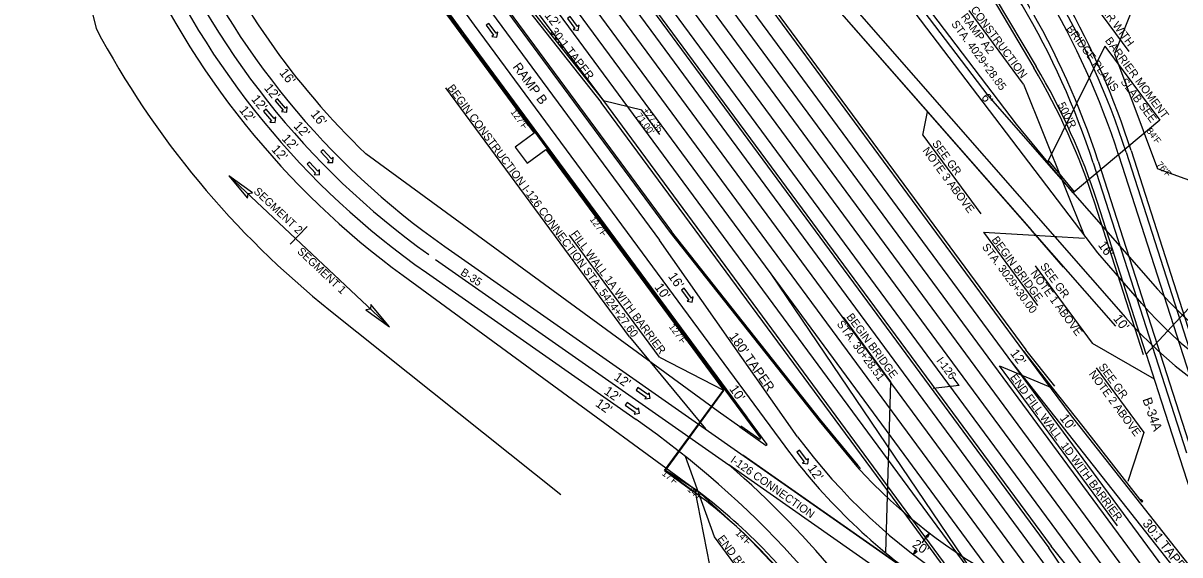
# Model space of a CAD drawing. Extents: x 1966090 to 1975830, y 788086 to 801233.
# Drawn here: x 1970278 to 1971145, y 796167 to 796566 of the extents above; entities that cross this region are included whole.
import ezdxf

# ---------------------------------------------------------------- set-up
doc = ezdxf.new("R2010")
doc.units = 0
for name, color, linetype in [('BR_PRESTRESSED BEAM', 7, 'Continuous'), ('BR_PROPOSED_DRAINAGE', 7, 'Continuous'), ('BR_REBAR', 7, 'Continuous'), ('RD_EX_Driveway_txCode', 7, 'Continuous'), ('RD_EX_RW_TX', 7, 'Continuous'), ('RD_EX_SU_Gas', 7, 'Continuous'), ('RD_EX_SU_H2O', 7, 'Continuous'), ('RD_EX_TX_Dam_ELEV', 7, 'Continuous'), ('RD_PD_PaveShd', 7, 'Continuous'), ('RD_PD_RW_TX', 7, 'Continuous'), ('RD_Sketch6', 7, 'Continuous'), ('RD_Sketch8', 7, 'Continuous'), ('RD_Sketch9', 7, 'Continuous')]:
    doc.layers.add(name, color=color, linetype=linetype)

msp = doc.modelspace()

# ---------------------------------------------------------------- linework, layer by layer
at = {"layer": 'BR_PRESTRESSED BEAM'}
for p, q in [((1970787.81, 796798.98), (1971022.06, 796490.5)), ((1970738.79, 796747.3), (1971033.24, 796411.1)), ((1971022.06, 796490.5), (1971045.64, 796461.99)), ((1971108.26, 796470.58), (1971155.03, 796325.07)), ((1971057.61, 796383.26), (1971033.24, 796411.1)), ((1971119.45, 796318.1), (1971130.78, 796282.88)), ((1971049.03, 796292.83), (1971071.97, 796263.8)), ((1971130.78, 796282.88), (1971152.81, 796214.33)), ((1971071.97, 796263.8), (1971116.28, 796207.05)), ((1971115.64, 796209.09), (1971115.05, 796208.63)), ((1971115.05, 796208.63), (1971116.28, 796207.05)), ((1971117.07, 796207.67), (1971115.64, 796209.09)), ((1971116.28, 796207.05), (1971117.07, 796207.67))]:
    msp.add_line(p, q, dxfattribs=at)
msp.add_arc((1970527.52, 796283.91), 610, 17.81866, 41.03874, dxfattribs=at)
at = {"layer": 'BR_PROPOSED_DRAINAGE'}
for p, q in [((1970591.97, 796577.07), (1970651.22, 796496.51)), ((1970651.22, 796496.51), (1970660.72, 796483.61)), ((1970660.72, 796483.61), (1970646.71, 796473.28)), ((1970646.71, 796473.28), (1970655.61, 796461.21)), ((1970655.61, 796461.21), (1970669.62, 796471.54)), ((1970669.62, 796471.54), (1970710.56, 796416.02)), ((1970710.56, 796416.02), (1970769.89, 796335.53)), ((1970769.89, 796335.53), (1970802.67, 796291.06)), ((1970802.67, 796291.06), (1970758.92, 796231.3)), ((1970758.92, 796231.3), (1970782.69, 796216.13)), ((1970782.69, 796216.13), (1970818.81, 796183)), ((1970818.81, 796183), (1970852.53, 796147.43))]:
    msp.add_line(p, q, dxfattribs=at)
for points in [[(1971119.79, 796603.55), (1971095.61, 796543.15), (1971127.85, 796457)], [(1971246.98, 796386.46), (1971192.99, 796433.53), (1971127.85, 796457)]]:
    msp.add_lwpolyline(points, dxfattribs=at)
at = {"layer": 'BR_REBAR'}
for p, q in [((1970693.11, 796777.07), (1971029.24, 796321.12)), ((1970691.5, 796775.88), (1971027.63, 796319.93)), ((1970540.77, 796722.24), (1970711.09, 796506.63)), ((1971003.51, 796586.33), (1971035.34, 796532.61)), ((1971005.19, 796587.41), (1971037.06, 796533.63)), ((1970636.89, 796579.98), (1970762.72, 796409.3)), ((1970637.8, 796580.65), (1970763.63, 796409.96)), ((1970607.11, 796558.02), (1970830.45, 796255.07)), ((1970607.92, 796558.62), (1970820.15, 796270.73)), ((1970937.02, 796200.16), (1970711.09, 796506.63)), ((1970712.68, 796507.84), (1971060.28, 796036.33)), ((1971045.64, 796461.99), (1971046.5, 796462.7)), ((1971064.75, 796438.86), (1971045.64, 796461.99)), ((1971046.5, 796462.7), (1971065.6, 796439.6)), ((1971065.6, 796439.6), (1971064.75, 796438.86)), ((1971117.55, 796317.49), (1971081.03, 796431.11)), ((1971119.45, 796318.1), (1971082.93, 796431.73)), ((1970762.72, 796409.3), (1970874.36, 796267.97)), ((1970763.6, 796409.99), (1970875.24, 796268.67)), ((1971027.48, 796320.12), (1971049.03, 796292.83)), ((1971029.05, 796321.35), (1971050.64, 796294.02)), ((1970758.49, 796230.72), (1970802.67, 796291.06)), ((1970759.19, 796230.82), (1970802.98, 796290.64)), ((1970874.36, 796267.97), (1970902.51, 796233.74)), ((1970875.23, 796268.69), (1970903.38, 796234.46)), ((1970815.58, 796264.21), (1970829.85, 796254.21)), ((1970830.45, 796255.07), (1970829.85, 796254.21)), ((1970758.49, 796230.72), (1970779.71, 796215.18)), ((1970759.19, 796230.82), (1970780.01, 796215.58)), ((1970902.51, 796233.74), (1970904.55, 796231.54)), ((1970903.34, 796234.51), (1970905.37, 796232.3)), ((1970779.71, 796215.18), (1970781.01, 796216.96)), ((1970937.02, 796200.16), (1971058.67, 796035.14))]:
    msp.add_line(p, q, dxfattribs=at)
for centre, radius, start, end in [((1972641.14, 798057.51), 2527, 211.39766, 216.39766), ((1972641.14, 798057.51), 2526, 211.39766, 216.39766), ((1970606.92, 796278.72), 498, 17.81866, 30.651), ((1970606.92, 796278.72), 500, 17.81866, 30.651), ((1970544.52, 795893.94), 398.34, 44.12328, 53.79058), ((1970544.52, 795893.94), 400.34, 44.12328, 53.79058), ((1970326.54, 795682.53), 702, 29.92814, 44.12328), ((1970326.54, 795682.53), 704, 29.92814, 44.12328)]:
    msp.add_arc(centre, radius, start, end, dxfattribs=at)
at = {"layer": 'RD_EX_Driveway_txCode'}
for p, q in [((1970951.62, 796176.58), (1970957.13, 796183.79)), ((1970957.13, 796183.79), (1970956.18, 796182.55)), ((1970944.99, 796167.9), (1970947.37, 796171.02)), ((1970944.99, 796167.9), (1970946.47, 796169.84))]:
    msp.add_line(p, q, dxfattribs=at)
for points in [[(1970687.76, 796571.06), (1970685.83, 796569.64), (1970691.27, 796562.26), (1970689.96, 796561.29), (1970693.91, 796560.69), (1970694.51, 796564.65), (1970693.2, 796563.68)], [(1970626.82, 796565.94), (1970624.88, 796564.53), (1970630.3, 796557.13), (1970628.99, 796556.16), (1970632.94, 796555.56), (1970633.55, 796559.51), (1970632.24, 796558.55)], [(1970468.56, 796509.41), (1970466.74, 796507.85), (1970472.72, 796500.89), (1970471.48, 796499.83), (1970475.47, 796499.53), (1970475.77, 796503.52), (1970474.54, 796502.46)], [(1970459.92, 796501.55), (1970458.1, 796499.99), (1970464.08, 796493.03), (1970462.84, 796491.97), (1970466.83, 796491.67), (1970467.13, 796495.66), (1970465.9, 796494.6)], [(1970502.66, 796471.2), (1970500.9, 796469.56), (1970507.15, 796462.85), (1970505.96, 796461.74), (1970509.96, 796461.6), (1970510.1, 796465.6), (1970508.91, 796464.49)], [(1970492.55, 796462.01), (1970490.8, 796460.38), (1970497.05, 796453.67), (1970495.86, 796452.56), (1970499.86, 796452.41), (1970500, 796456.41), (1970498.81, 796455.3)], [(1970773.2, 796367.38), (1970771.26, 796365.97), (1970776.68, 796358.57), (1970775.37, 796357.61), (1970779.32, 796357), (1970779.93, 796360.95), (1970778.62, 796359.99)], [(1970738.55, 796292.95), (1970737.17, 796290.99), (1970744.69, 796285.72), (1970743.75, 796284.39), (1970747.69, 796285.08), (1970747, 796289.02), (1970746.06, 796287.69)], [(1970730.5, 796281.65), (1970729.12, 796279.69), (1970736.63, 796274.43), (1970735.7, 796273.09), (1970739.64, 796273.79), (1970738.94, 796277.73), (1970738.01, 796276.39)], [(1970859.69, 796246.04), (1970857.75, 796244.62), (1970863.17, 796237.23), (1970861.86, 796236.26), (1970865.81, 796235.65), (1970866.42, 796239.61), (1970865.11, 796238.65)], [(1970954.31, 796181.54), (1970957.13, 796183.79), (1970955.7, 796180.48)], [(1970947.81, 796170.15), (1970944.99, 796167.9), (1970946.42, 796171.21)]]:
    msp.add_lwpolyline(points, close=True, dxfattribs=at)
at = {"layer": 'RD_EX_SU_Gas'}
for p, q in [((1970514.75, 796954.97), (1971123.99, 796128.55)), ((1970505.09, 796947.85), (1971239.95, 795951.02)), ((1970468.06, 796920.55), (1971202.93, 795923.73)), ((1970458.41, 796913.43), (1971193.27, 795916.61)), ((1970586.97, 796388.95), (1970806.83, 796234.93)), ((1970838.13, 796378.12), (1971016.36, 796136.35))]:
    msp.add_line(p, q, dxfattribs=at)
msp.add_arc((1970931.23, 796880.36), 600, 202.42407, 234.38356, dxfattribs=at)
at = {"layer": 'RD_EX_TX_Dam_ELEV'}
for p, q in [((1970277.87, 796788.53), (1970332.59, 796562.06)), ((1970508.15, 796350.56), (1970680.78, 796212.71))]:
    msp.add_line(p, q, dxfattribs=at)
msp.add_arc((1970931.23, 796880.36), 678, 207.99975, 231.39029, dxfattribs=at)
at = {"layer": 'RD_PD_PaveShd'}
for p, q in [((1970614.81, 797020.2), (1971000.85, 796511.82)), ((1970485.77, 796933.61), (1971046.58, 796172.88)), ((1970487.38, 796934.79), (1971048.19, 796174.06)), ((1970664.28, 796832.37), (1971096.42, 796338.96)), ((1970691.5, 796775.88), (1971027.63, 796319.93)), ((1970535.72, 796731.87), (1970712.68, 796507.84)), ((1970636.89, 796579.98), (1970762.72, 796409.3)), ((1970607.92, 796558.62), (1970835.24, 796250.26)), ((1971000.85, 796511.82), (1971128.01, 796366.63)), ((1970712.68, 796507.84), (1971060.28, 796036.33)), ((1970798.68, 796274.87), (1970534.56, 796468.25)), ((1971104.45, 796469.35), (1971162.54, 796288.62)), ((1971079.7, 796461.4), (1971149.56, 796244.06)), ((1970762.72, 796409.3), (1970874.36, 796267.97)), ((1970562.6, 796376.87), (1970781.01, 796216.96)), ((1971027.63, 796319.93), (1971063.23, 796271.64)), ((1970815.01, 796263.39), (1970798.68, 796274.87)), ((1971063.23, 796271.64), (1971208.88, 796087.26)), ((1970815.01, 796263.39), (1970834.74, 796249.56)), ((1970835.24, 796250.26), (1970834.77, 796249.6)), ((1971083.53, 796118.12), (1971046.58, 796172.88)), ((1971089.57, 796122.57), (1971048.19, 796174.06))]:
    msp.add_line(p, q, dxfattribs=at)
for centre, radius, start, end in [((1972641.14, 798057.51), 2526, 211.39766, 216.39766), ((1970527.52, 796283.91), 606, 17.81866, 43.48334), ((1970527.52, 796283.91), 580, 17.81866, 43.48334), ((1970931.23, 796880.36), 572, 203.65523, 226.09408), ((1970931.23, 796880.36), 624, 203.63926, 233.79058), ((1971210.82, 796516.01), 418, 222.47514, 298.92325), ((1970544.52, 795893.94), 400.34, 44.12328, 53.79058), ((1970326.54, 795682.53), 704, 29.92814, 44.12328)]:
    msp.add_arc(centre, radius, start, end, dxfattribs=at)
at = {"layer": 'RD_PD_RW_TX'}
msp.add_arc((1971352.19, 796562.97), 298, 221.21202, 301.34068, dxfattribs=at)
at = {"layer": 'RD_Sketch6'}
for p, q in [((1971106.66, 796544.92), (1971052.71, 796618.09)), ((1971027.48, 796520.46), (1970986.8, 796575.64)), ((1971088.6, 796548.84), (1971045.64, 796461.99)), ((1971088.6, 796548.84), (1971129.65, 796493.54)), ((1970732.38, 796330.87), (1970594.71, 796517.63)), ((1971027.48, 796520.46), (1971073.32, 796406.47)), ((1970952.21, 796482.13), (1970955.71, 796499.62)), ((1971129.65, 796493.54), (1971064.75, 796438.86)), ((1970952.21, 796482.13), (1970995.6, 796423.27)), ((1970482.09, 796404.65), (1970432.09, 796451.79)), ((1970432.09, 796451.79), (1970446.02, 796434.83)), ((1970449.86, 796438.91), (1970432.09, 796451.79)), ((1970446.38, 796438.32), (1970449.86, 796438.91)), ((1970446.02, 796434.83), (1970446.38, 796438.32)), ((1970478.08, 796400.39), (1970490.62, 796413.69)), ((1970552.39, 796338.37), (1970482.09, 796404.65)), ((1970754.71, 796315.75), (1970687.25, 796407.25)), ((1970997.52, 796409.45), (1971073.22, 796404.91)), ((1970997.52, 796409.45), (1971037.97, 796354.58)), ((1971119.45, 796318.1), (1971205.42, 796410.94)), ((1971036.26, 796384.29), (1971079.05, 796326.25)), ((1970538.47, 796355.33), (1970538.11, 796351.84)), ((1970552.39, 796338.37), (1970538.47, 796355.33)), ((1970538.11, 796351.84), (1970534.62, 796351.25)), ((1970534.62, 796351.25), (1970552.39, 796338.37)), ((1970892.27, 796345.62), (1970927.9, 796297.29)), ((1970732.38, 796330.87), (1970789.2, 796261.93)), ((1971079.05, 796326.25), (1971125.41, 796299.57)), ((1970754.71, 796315.75), (1970802.67, 796291.06)), ((1971098.07, 796189.3), (1971009.59, 796309.33)), ((1971009.59, 796309.33), (1971049.03, 796292.83)), ((1970979.29, 796294.53), (1970974.9, 796300.45)), ((1971082.08, 796307.73), (1971117.73, 796259.37)), ((1970927.9, 796297.29), (1970924.22, 796169.08)), ((1970979.29, 796294.53), (1970959.92, 796292.12)), ((1971117.73, 796259.37), (1971105.71, 796222.43)), ((1970795.89, 796181.09), (1970774.14, 796241.38)), ((1970792.45, 796159.71), (1970781.29, 796217.33)), ((1970866.98, 796084.66), (1970795.89, 796181.09))]:
    msp.add_line(p, q, dxfattribs=at)
msp.add_lwpolyline([(1970754.95, 796482.78), (1970741.63, 796500.84), (1970712.68, 796507.84)], dxfattribs=at)
at = {"layer": 'RD_Sketch8'}
for p, q in [((1970331.93, 797227.03), (1971103.94, 796345.55)), ((1970499.5, 797162.12), (1971082.9, 796393.86)), ((1970534.07, 796969.21), (1971268.93, 795972.38)), ((1970524.41, 796962.09), (1971259.27, 795965.26)), ((1970495.43, 796940.73), (1971230.29, 795943.9)), ((1970477.72, 796927.67), (1971212.58, 795930.85)), ((1970439.11, 796899.16), (1970686.58, 796563.47)), ((1970448.75, 796906.31), (1970838.13, 796378.12)), ((1970461.73, 796844.88), (1970712.68, 796507.84)), ((1970628.84, 796574.04), (1970754.67, 796403.36)), ((1970615.97, 796564.55), (1970848.6, 796248.98)), ((1970686.68, 796563.34), (1971173.95, 795902.36)), ((1971098.74, 796467.52), (1971168.6, 796250.18)), ((1971083.51, 796462.62), (1971153.36, 796245.28)), ((1970593.86, 796398.78), (1970952.62, 796147.45)), ((1970858.26, 796256.1), (1970754.67, 796403.36)), ((1971082.9, 796393.86), (1971115.97, 796356.09)), ((1970580.09, 796379.12), (1970737.35, 796268.95)), ((1970838.13, 796378.12), (1971006.7, 796129.23)), ((1971018.07, 796312.68), (1971241.34, 796030.03)), ((1970952.62, 796147.45), (1970817.21, 796242.31)), ((1970945.74, 796137.62), (1970806.83, 796234.93))]:
    msp.add_line(p, q, dxfattribs=at)
for centre, radius, start, end in [((1972641.14, 798057.51), 2516, 211.39766, 216.39766), ((1970527.52, 796283.91), 600, 17.81866, 43.48334), ((1970527.52, 796283.91), 584, 17.81866, 43.48334), ((1970931.23, 796880.36), 588, 203.63926, 234.98689), ((1970931.23, 796880.36), 612, 203.63926, 234.98689), ((1971352.19, 796562.97), 314, 221.21202, 318.86296), ((1971352.19, 796562.97), 330, 221.21202, 316.81039), ((1970326.54, 795682.53), 716, 29.92814, 54.98689), ((1971210.82, 796516.01), 450, 216.39766, 234.98689), ((1971210.82, 796516.01), 438, 216.39766, 298.92325), ((1970326.54, 795682.53), 732, 29.92814, 48.99436)]:
    msp.add_arc(centre, radius, start, end, dxfattribs=at)
at = {"layer": 'RD_Sketch9'}
for p, q in [((1970485.77, 796933.61), (1971046.58, 796172.88)), ((1970487.38, 796934.79), (1971048.19, 796174.06))]:
    msp.add_line(p, q, dxfattribs=at)

# ---------------------------------------------------------------- texts
at = {"layer": 'RD_EX_Driveway_txCode'}
for s, height, rotation, p in [("12'", 7, 307.53305, (1970668.15, 796571.98)), ('30:1 TAPER', 6.3, 307.99769, (1970672.43, 796559.85)), ("16'", 7, 308.77906, (1970469.49, 796528.81)), ("12'", 7, 308.77906, (1970458, 796517.37)), ("12'", 7, 308.77906, (1970448.39, 796509.05)), ("6'", 7, 305.3319, (1970995.55, 796510.42)), ("12'", 7, 308.77906, (1970439.38, 796500.84)), ("16'", 7, 308.77906, (1970492.88, 796497.76)), ("12'", 7, 312.98004, (1970480.09, 796488.61)), ("12'", 7, 312.98004, (1970471.23, 796479.16)), ("12'", 7, 312.98004, (1970463.44, 796471.08)), ("16'", 7, 305.3319, (1971083.1, 796399.76)), ("16'", 7, 304.83624, (1970760.86, 796376.33)), ("10'", 7, 304.83624, (1970750.68, 796368.23)), ("10'", 7, 307.53142, (1971094.39, 796344.53)), ("180' TAPER", 7, 304.83624, (1970806.56, 796331.27)), ("12'", 7, 306.39925, (1971017.2, 796318.6)), ("12'", 7, 324.98663, (1970720.01, 796299.31)), ("12'", 7, 324.98663, (1970712.59, 796288.74)), ("10'", 7, 304.83624, (1970806.77, 796291.94)), ("12'", 7, 324.98663, (1970706.15, 796279.57)), ('B-34A', 7, 289.1995, (1971116.57, 796284.11)), ("10'", 7, 306.39925, (1971054.37, 796270)), ('I-126 CONNECTION', 5.9996, 324.94106, (1970807.39, 796237.4)), ("12'", 7, 304.83624, (1970865.41, 796232.35)), ('30:1 TAPER', 7, 308.30681, (1971116.34, 796190.87)), ("20'", 7, 326.14848, (1970943.62, 796173.89))]:
    msp.add_text(s, height=height, rotation=rotation, dxfattribs=at).set_placement(p)
at = {"layer": 'RD_EX_RW_TX'}
for s, rotation, p in [("127'F", 306.39766, (1970642.87, 796499.41)), ("84'F", 307.21202, (1971119.38, 796485.24)), ("76'F", 311.21202, (1971126.77, 796459.83)), ("127'F", 306.39766, (1970702.2, 796418.92)), ("127'F", 306.39766, (1970761.54, 796338.43)), ("17'F", 321.30742, (1970756.19, 796227.85)), ("14'F", 319.47412, (1970775.23, 796215.94)), ("14'F", 315.47301, (1970811.35, 796183.33))]:
    msp.add_text(s, height=5, rotation=rotation, dxfattribs=at).set_placement(p)
at = {"layer": 'RD_EX_SU_H2O'}
msp.add_text('RAMP B', height=7, rotation=306.46788, dxfattribs=at).set_placement((1970644.4, 796533.3))
at = {"layer": 'RD_Sketch6'}
for s, height, rotation, p in [('BEGIN BARRIER WITH ', 5.9996, 306.55744, (1971055.14, 796616.89)), ('CONSTRUCTION', 5.9996, 306.55916, (1970987.56, 796576.2)), ('RAMP A2 ', 6, 306.55916, (1970980.33, 796570.84)), ('STA. 4029+28.85', 5.9996, 306.55916, (1970973.1, 796565.48)), ('          BRIDGE PLANS', 5.9996, 306.55744, (1971045.99, 796579.84)), ('BARRIER MOMENT', 5.9996, 306.55744, (1971088.3, 796552.99)), ('BEGIN CONSTRUCTION I-126 CONNECTION STA. 5424+27.60', 5.9996, 306.55916, (1970595.49, 796517.5)), ('SLAB SEE ', 6, 306.55744, (1971099.97, 796522.15)), ('+27.35', 5, 306.3977, (1970741.93, 796500.43)), ("500'R", 6, 296.95176, (1971052.89, 796505.07)), ("71.00'", 5, 306.3977, (1970736.66, 796496.54)), ('NOTE 3 ABOVE', 5.9996, 306.42425, (1970951.52, 796470.51)), ('SEE GR ', 6, 306.42425, (1970958.76, 796475.85)), ('SEGMENT 2', 6, 316.7437, (1970450.1, 796439.4)), (' FILL WALL 1A WITH BARRIER', 5.9996, 306.55744, (1970686.67, 796409.82)), ('BEGIN BRIDGE', 5.9996, 306.42425, (1971003.36, 796403.66)), ('SEGMENT 1', 6, 316.7437, (1970482.77, 796394.38)), ('STA. 3029+30.00', 5.9996, 306.42425, (1970996.12, 796398.32)), ('B-35', 6, 326.92608, (1970605.07, 796377.86)), ('NOTE 1 ABOVE', 5.9996, 306.42425, (1971032.4, 796378.46)), ('SEE GR ', 6, 306.42425, (1971039.64, 796383.8)), ('BEGIN BRIDGE', 5.9996, 306.42425, (1970894.54, 796345.92)), ('STA. 30+28.51', 5.9996, 306.42425, (1970887.3, 796340.58)), ('I-126', 6, 306.59614, (1970961.94, 796313.07)), ('SEE GR ', 6, 306.42425, (1971083.46, 796308.45)), ('END FILL WALL  1D WITH BARRIER', 5.9996, 306.55744, (1971017.17, 796300.49)), ('NOTE 2 ABOVE', 5.9996, 306.42425, (1971076.22, 796303.11)), ('END BRIDGE STA. 5424+27.09', 5.9996, 306.55744, (1970797.94, 796179.59))]:
    msp.add_text(s, height=height, rotation=rotation, dxfattribs=at).set_placement(p)

doc.saveas('drawing.dxf')
